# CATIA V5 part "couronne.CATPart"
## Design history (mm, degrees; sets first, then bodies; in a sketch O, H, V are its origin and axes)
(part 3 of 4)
    point P475 (-49.0081, -10.3827)
    point P476 (-49.0081, -10.3827)
    point P477 (-49.0641, -10.4563)
    point P478 (-49.0641, -10.4563)
    point P479 (-49.1276, -10.6804)
    point P480 (-49.1276, -10.6804)
    point P485 (-48.959, -11.1964)
    point P486 (-48.959, -11.1964)
    point P487 (-48.8349, -11.2887)
    point P488 (-48.8349, -11.2887)
    point P489 (-48.7903, -11.3063)
    point P490 (-48.7903, -11.3063)
    point P491 (-48.7658, -11.3115)
    point P492 (-48.7658, -11.3115)
    point P493 (-48.4661, -11.3684)
    point P494 (-48.4661, -11.3684)
    point P495 (-48.1321, -11.4258)
    point P496 (-48.1321, -11.4258)
    point P497 (-47.811, -11.4752)
    point P498 (-47.811, -11.4752)
    point P499 (-47.5029, -11.5172)
    point P500 (-47.5029, -11.5172)
    point P501 (-47.2079, -11.5521)
    point P502 (-47.2079, -11.5521)
    point P503 (-46.9261, -11.5805)
    point P504 (-46.9261, -11.5805)
    point P505 (-46.6578, -11.6028)
    point P506 (-46.6578, -11.6028)
    point P507 (-46.403, -11.6195)
    point P508 (-46.403, -11.6195)
    point P509 (-46.1619, -11.631)
    point P510 (-46.1619, -11.631)
    point P511 (-45.9345, -11.638)
    point P512 (-45.9345, -11.638)
    point P517 (-45.5064, -12.8325)
    point P518 (-45.5064, -12.8325)
    point P519 (-45.6949, -12.9469)
    point P520 (-45.6949, -12.9469)
    point P521 (-45.8932, -13.0721)
    point P522 (-45.8932, -13.0721)
    point P523 (-46.1009, -13.2083)
    point P524 (-46.1009, -13.2083)
    point P525 (-46.3177, -13.3559)
    point P526 (-46.3177, -13.3559)
    point P527 (-46.5433, -13.5153)
    point P528 (-46.5433, -13.5153)
    point P529 (-46.7773, -13.6868)
    point P530 (-46.7773, -13.6868)
    point P531 (-47.0193, -13.8709)
    point P532 (-47.0193, -13.8709)
    point P533 (-47.269, -14.0677)
    point P534 (-47.269, -14.0677)
    point P535 (-47.526, -14.2777)
    point P536 (-47.526, -14.2777)
    point P537 (-47.7899, -14.5011)
    point P538 (-47.7899, -14.5011)
    point P539 (-47.9051, -14.6021)
    point P540 (-47.9051, -14.6021)
    point P541 (-47.9167, -14.6146)
    point P542 (-47.9167, -14.6146)
    point P543 (-47.9661, -14.6927)
    point P544 (-47.9661, -14.6927)
    point P545 (-48.0098, -14.9215)
    point P546 (-48.0098, -14.9215)
    point P551 (-47.7969, -15.4209)
    point P552 (-47.7969, -15.4209)
    point P553 (-47.6652, -15.502)
    point P554 (-47.6652, -15.502)
    point P555 (-47.6192, -15.5156)
    point P556 (-47.6192, -15.5156)
    point P557 (-47.5944, -15.5187)
    point P558 (-47.5944, -15.5187)
    point P559 (-47.2908, -15.5493)
    point P560 (-47.2908, -15.5493)
    point P561 (-46.9532, -15.5773)
    point P562 (-46.9532, -15.5773)
    point P563 (-46.629, -15.5986)
    point P564 (-46.629, -15.5986)
    point P565 (-46.3183, -15.6135)
    point P566 (-46.3183, -15.6135)
    point P567 (-46.0214, -15.6226)
    point P568 (-46.0214, -15.6226)
    point P569 (-45.7383, -15.6263)
    point P570 (-45.7383, -15.6263)
    point P571 (-45.469, -15.6251)
    point P572 (-45.469, -15.6251)
    point P573 (-45.2137, -15.6195)
    point P574 (-45.2137, -15.6195)
    point P575 (-44.9725, -15.6101)
    point P576 (-44.9725, -15.6101)
    point P577 (-44.7453, -15.5972)
    point P578 (-44.7453, -15.5972)
    point P583 (-44.2148, -16.7498)
    point P584 (-44.2148, -16.7498)
    point P585 (-44.3926, -16.8803)
    point P586 (-44.3926, -16.8803)
    point P587 (-44.5793, -17.0222)
    point P588 (-44.5793, -17.0222)
    point P589 (-44.7743, -17.176)
    point P590 (-44.7743, -17.176)
    point P591 (-44.9775, -17.3419)
    point P592 (-44.9775, -17.3419)
    point P593 (-45.1883, -17.5204)
    point P594 (-45.1883, -17.5204)
    point P595 (-45.4064, -17.7117)
    point P596 (-45.4064, -17.7117)
    point P597 (-45.6314, -17.9161)
    point P598 (-45.6314, -17.9161)
    point P599 (-45.863, -18.1339)
    point P600 (-45.863, -18.1339)
    point P601 (-46.1007, -18.3655)
    point P602 (-46.1007, -18.3655)
    point P603 (-46.3442, -18.6111)
    point P604 (-46.3442, -18.6111)
    point P605 (-46.4502, -18.7218)
    point P606 (-46.4502, -18.7218)
    point P607 (-46.4606, -18.7352)
    point P608 (-46.4606, -18.7352)
    point P609 (-46.503, -18.8173)
    point P610 (-46.503, -18.8173)
    point P611 (-46.5266, -19.049)
    point P612 (-46.5266, -19.049)
    point P617 (-46.271, -19.5279)
    point P618 (-46.271, -19.5279)
    point P619 (-46.1327, -19.5973)
    point P620 (-46.1327, -19.5973)
    point P621 (-46.0858, -19.6068)
    point P622 (-46.0858, -19.6068)
    point P623 (-46.0608, -19.6078)
    point P624 (-46.0608, -19.6078)
    point P625 (-45.7556, -19.6118)
    point P626 (-45.7556, -19.6118)
    point P627 (-45.4168, -19.6103)
    point P628 (-45.4168, -19.6103)
    point P629 (-45.092, -19.6032)
    point P630 (-45.092, -19.6032)
    point P631 (-44.7813, -19.591)
    point P632 (-44.7813, -19.591)
    point P633 (-44.4847, -19.5742)
    point P634 (-44.4847, -19.5742)
    point P635 (-44.2023, -19.5532)
    point P636 (-44.2023, -19.5532)
    point P637 (-43.9342, -19.5285)
    point P638 (-43.9342, -19.5285)
    point P639 (-43.6803, -19.5007)
    point P640 (-43.6803, -19.5007)
    point P641 (-43.4409, -19.4703)
    point P642 (-43.4409, -19.4703)
    point P643 (-43.2157, -19.4376)
    point P644 (-43.2157, -19.4376)
    point P649 (-42.5867, -20.5397)
    point P650 (-42.5867, -20.5397)
    point P651 (-42.7525, -20.6851)
    point P652 (-42.7525, -20.6851)
    point P653 (-42.9261, -20.8427)
    point P654 (-42.9261, -20.8427)
    point P655 (-43.107, -21.0129)
    point P656 (-43.107, -21.0129)
    point P657 (-43.2949, -21.196)
    point P658 (-43.2949, -21.196)
    point P659 (-43.4893, -21.3921)
    point P660 (-43.4893, -21.3921)
    point P661 (-43.6899, -21.6017)
    point P662 (-43.6899, -21.6017)
    point P663 (-43.8963, -21.8249)
    point P664 (-43.8963, -21.8249)
    point P665 (-44.108, -22.0622)
    point P666 (-44.108, -22.0622)
    point P667 (-44.3246, -22.3136)
    point P668 (-44.3246, -22.3136)
    point P669 (-44.5457, -22.5794)
    point P670 (-44.5457, -22.5794)
    point P671 (-44.6417, -22.6989)
    point P672 (-44.6417, -22.6989)
    point P673 (-44.6509, -22.7132)
    point P674 (-44.6509, -22.7132)
    point P675 (-44.686, -22.7987)
    point P676 (-44.686, -22.7987)
    point P677 (-44.6894, -23.0316)
    point P678 (-44.6894, -23.0316)
    point P683 (-44.3929, -23.4864)
    point P684 (-44.3929, -23.4864)
    point P685 (-44.2491, -23.5435)
    point P686 (-44.2491, -23.5435)
    point P687 (-44.2015, -23.5489)
    point P688 (-44.2015, -23.5489)
    point P689 (-44.1766, -23.5476)
    point P690 (-44.1766, -23.5476)
    point P691 (-43.8723, -23.525)
    point P692 (-43.8723, -23.525)
    point P693 (-43.5349, -23.494)
    point P694 (-43.5349, -23.494)
    point P695 (-43.2119, -23.4586)
    point P696 (-43.2119, -23.4586)
    point P697 (-42.9034, -23.4194)
    point P698 (-42.9034, -23.4194)
    point P699 (-42.6094, -23.3768)
    point P700 (-42.6094, -23.3768)
    point P701 (-42.3299, -23.3313)
    point P702 (-42.3299, -23.3313)
    point P703 (-42.065, -23.2833)
    point P704 (-42.065, -23.2833)
    point P705 (-41.8145, -23.2335)
    point P706 (-41.8145, -23.2335)
    point P707 (-41.5786, -23.1823)
    point P708 (-41.5786, -23.1823)
    point P709 (-41.3571, -23.1302)
    point P710 (-41.3571, -23.1302)
    point P715 (-40.6345, -24.1732)
    point P716 (-40.6345, -24.1732)
    point P717 (-40.787, -24.3325)
    point P718 (-40.787, -24.3325)
    point P719 (-40.9461, -24.5047)
    point P720 (-40.9461, -24.5047)
    point P721 (-41.1115, -24.69)
    point P722 (-41.1115, -24.69)
    point P723 (-41.2828, -24.8887)
    point P724 (-41.2828, -24.8887)
    point P725 (-41.4594, -25.1011)
    point P726 (-41.4594, -25.1011)
    point P727 (-41.641, -25.3273)
    point P728 (-41.641, -25.3273)
    point P729 (-41.8271, -25.5677)
    point P730 (-41.8271, -25.5677)
    point P731 (-42.0173, -25.8225)
    point P732 (-42.0173, -25.8225)
    point P733 (-42.2112, -26.0918)
    point P734 (-42.2112, -26.0918)
    point P735 (-42.4083, -26.3759)
    point P736 (-42.4083, -26.3759)
    point P737 (-42.4935, -26.5033)
    point P738 (-42.4935, -26.5033)
    point P739 (-42.5014, -26.5183)
    point P740 (-42.5014, -26.5183)
    point P741 (-42.5289, -26.6066)
    point P742 (-42.5289, -26.6066)
    point P743 (-42.512, -26.8389)
    point P744 (-42.512, -26.8389)
    point P749 (-42.177, -27.2661)
    point P750 (-42.177, -27.2661)
    point P751 (-42.0288, -27.3105)
    point P752 (-42.0288, -27.3105)
    point P753 (-41.9809, -27.3117)
    point P754 (-41.9809, -27.3117)
    point P755 (-41.9561, -27.3083)
    point P756 (-41.9561, -27.3083)
    point P757 (-41.655, -27.2592)
    point P758 (-41.655, -27.2592)
    point P759 (-41.3216, -27.1989)
    point P760 (-41.3216, -27.1989)
    point P761 (-41.0029, -27.1355)
    point P762 (-41.0029, -27.1355)
    point P763 (-40.699, -27.0696)
    point P764 (-40.699, -27.0696)
    point P765 (-40.4098, -27.0015)
    point P766 (-40.4098, -27.0015)
    point P767 (-40.1354, -26.9318)
    point P768 (-40.1354, -26.9318)
    point P769 (-39.8756, -26.8609)
    point P770 (-39.8756, -26.8609)
    point P771 (-39.6305, -26.7895)
    point P772 (-39.6305, -26.7895)
    point P773 (-39.3999, -26.7179)
    point P774 (-39.3999, -26.7179)
    point P775 (-39.1838, -26.6466)
    point P776 (-39.1838, -26.6466)
    point P781 (-38.373, -27.6227)
    point P782 (-38.373, -27.6227)
    point P783 (-38.5111, -27.7947)
    point P784 (-38.5111, -27.7947)
    point P785 (-38.6546, -27.9801)
    point P786 (-38.6546, -27.9801)
    point P787 (-38.8032, -28.1791)
    point P788 (-38.8032, -28.1791)
    point P789 (-38.9565, -28.392)
    point P790 (-38.9565, -28.392)
    point P791 (-39.1139, -28.619)
    point P792 (-39.1139, -28.619)
    point P793 (-39.2751, -28.8602)
    point P794 (-39.2751, -28.8602)
    point P795 (-39.4396, -29.1159)
    point P796 (-39.4396, -29.1159)
    point P797 (-39.6069, -29.3863)
    point P798 (-39.6069, -29.3863)
    point P799 (-39.7765, -29.6715)
    point P800 (-39.7765, -29.6715)
    point P801 (-39.9481, -29.9716)
    point P802 (-39.9481, -29.9716)
    point P803 (-40.0218, -30.106)
    point P804 (-40.0218, -30.106)
    point P805 (-40.0285, -30.1217)
    point P806 (-40.0285, -30.1217)
    point P807 (-40.0482, -30.212)
    point P808 (-40.0482, -30.212)
    point P809 (-40.011, -30.4419)
    point P810 (-40.011, -30.4419)
    point P815 (-39.6401, -30.8384)
    point P816 (-39.6401, -30.8384)
    point P817 (-39.4886, -30.8696)
    point P818 (-39.4886, -30.8696)
    point P819 (-39.4408, -30.8666)
    point P820 (-39.4408, -30.8666)
    point P821 (-39.4164, -30.8611)
    point P822 (-39.4164, -30.8611)
    point P823 (-39.1207, -30.786)
    point P824 (-39.1207, -30.786)
    point P825 (-38.7938, -30.6968)
    point P826 (-38.7938, -30.6968)
    point P827 (-38.4819, -30.6059)
    point P828 (-38.4819, -30.6059)
    point P829 (-38.1849, -30.5137)
    point P830 (-38.1849, -30.5137)
    point P831 (-37.9027, -30.4207)
    point P832 (-37.9027, -30.4207)
    point P833 (-37.6354, -30.3273)
    point P834 (-37.6354, -30.3273)
    point P835 (-37.3828, -30.2341)
    point P836 (-37.3828, -30.2341)
    point P837 (-37.1448, -30.1416)
    point P838 (-37.1448, -30.1416)
    point P839 (-36.9214, -30.0502)
    point P840 (-36.9214, -30.0502)
    point P841 (-36.7123, -29.9603)
    point P842 (-36.7123, -29.9603)
    point P847 (-35.8195, -30.862)
    point P848 (-35.8195, -30.862)
    point P849 (-35.942, -31.0454)
    point P850 (-35.942, -31.0454)
    point P851 (-36.0689, -31.2426)
    point P852 (-36.0689, -31.2426)
    point P853 (-36.1996, -31.4538)
    point P854 (-36.1996, -31.4538)
    point P855 (-36.3337, -31.6793)
    point P856 (-36.3337, -31.6793)
    point P857 (-36.4708, -31.9191)
    point P858 (-36.4708, -31.9191)
    point P859 (-36.6103, -32.1734)
    point P860 (-36.6103, -32.1734)
    point P861 (-36.7519, -32.4425)
    point P862 (-36.7519, -32.4425)
    point P863 (-36.895, -32.7264)
    point P864 (-36.895, -32.7264)
    point P865 (-37.0391, -33.0253)
    point P866 (-37.0391, -33.0253)
    point P867 (-37.1839, -33.3393)
    point P868 (-37.1839, -33.3393)
    point P869 (-37.2456, -33.4796)
    point P870 (-37.2456, -33.4796)
    point P871 (-37.2509, -33.4958)
    point P872 (-37.2509, -33.4958)
    point P873 (-37.2626, -33.5874)
    point P874 (-37.2626, -33.5874)
    point P875 (-37.2056, -33.8133)
    point P876 (-37.2056, -33.8133)
    point P881 (-36.8016, -34.1759)
    point P882 (-36.8016, -34.1759)
    point P883 (-36.6479, -34.1938)
    point P884 (-36.6479, -34.1938)
    point P885 (-36.6005, -34.1867)
    point P886 (-36.6005, -34.1867)
    point P887 (-36.5767, -34.179)
    point P888 (-36.5767, -34.179)
    point P889 (-36.2886, -34.0784)
    point P890 (-36.2886, -34.0784)
    point P891 (-35.9708, -33.9611)
    point P892 (-35.9708, -33.9611)
    point P893 (-35.6679, -33.8434)
    point P894 (-35.6679, -33.8434)
    point P895 (-35.3801, -33.7256)
    point P896 (-35.3801, -33.7256)
    point P897 (-35.1072, -33.6083)
    point P898 (-35.1072, -33.6083)
    point P899 (-34.849, -33.492)
    point P900 (-34.849, -33.492)
    point P901 (-34.6055, -33.3772)
    point P902 (-34.6055, -33.3772)
    point P903 (-34.3765, -33.2643)
    point P904 (-34.3765, -33.2643)
    point P905 (-34.1618, -33.1537)
    point P906 (-34.1618, -33.1537)
    point P907 (-33.9614, -33.046)
    point P908 (-33.9614, -33.046)
    point P913 (-32.9934, -33.8665)
    point P914 (-32.9934, -33.8665)
    point P915 (-33.0995, -34.0598)
    point P916 (-33.0995, -34.0598)
    point P917 (-33.2087, -34.2674)
    point P918 (-33.2087, -34.2674)
    point P919 (-33.3205, -34.4892)
    point P920 (-33.3205, -34.4892)
    point P921 (-33.4344, -34.7254)
    point P922 (-33.4344, -34.7254)
    point P923 (-33.55, -34.9762)
    point P924 (-33.55, -34.9762)
    point P925 (-33.6669, -35.2418)
    point P926 (-33.6669, -35.2418)
    point P927 (-33.7845, -35.5222)
    point P928 (-33.7845, -35.5222)
    point P929 (-33.9023, -35.8175)
    point P930 (-33.9023, -35.8175)
    point P931 (-34.0199, -36.1278)
    point P932 (-34.0199, -36.1278)
    point P933 (-34.1367, -36.4532)
    point P934 (-34.1367, -36.4532)
    point P935 (-34.186, -36.5984)
    point P936 (-34.186, -36.5984)
    point P937 (-34.1898, -36.6149)
    point P938 (-34.1898, -36.6149)
    point P939 (-34.1935, -36.7073)
    point P940 (-34.1935, -36.7073)
    point P941 (-34.117, -36.9273)
    point P942 (-34.117, -36.9273)
    point P947 (-33.6829, -37.2533)
    point P948 (-33.6829, -37.2533)
    point P949 (-33.5283, -37.2577)
    point P950 (-33.5283, -37.2577)
    point P951 (-33.4817, -37.2465)
    point P952 (-33.4817, -37.2465)
    point P953 (-33.4586, -37.2368)
    point P954 (-33.4586, -37.2368)
    point P955 (-33.1804, -37.1115)
    point P956 (-33.1804, -37.1115)
    point P957 (-32.874, -36.967)
    point P958 (-32.874, -36.967)
    point P959 (-32.5826, -36.8233)
    point P960 (-32.5826, -36.8233)
    point P961 (-32.3061, -36.6809)
    point P962 (-32.3061, -36.6809)
    point P963 (-32.0444, -36.5402)
    point P964 (-32.0444, -36.5402)
    point P965 (-31.7974, -36.4019)
    point P966 (-31.7974, -36.4019)
    point P967 (-31.5648, -36.2662)
    point P968 (-31.5648, -36.2662)
    point P969 (-31.3465, -36.1338)
    point P970 (-31.3465, -36.1338)
    point P971 (-31.1423, -36.005)
    point P972 (-31.1423, -36.005)
    point P973 (-30.952, -35.8802)
    point P974 (-30.952, -35.8802)
    point P979 (-29.9162, -36.6132)
    point P980 (-29.9162, -36.6132)
    point P981 (-30.005, -36.815)
    point P982 (-30.005, -36.815)
    point P983 (-30.0957, -37.0313)
    point P984 (-30.0957, -37.0313)
    point P985 (-30.1877, -37.262)
    point P986 (-30.1877, -37.262)
    point P987 (-30.2807, -37.5073)
    point P988 (-30.2807, -37.5073)
    point P989 (-30.374, -37.7672)
    point P990 (-30.374, -37.7672)
    point P991 (-30.4673, -38.0419)
    point P992 (-30.4673, -38.0419)
    point P993 (-30.5599, -38.3315)
    point P994 (-30.5599, -38.3315)
    point P995 (-30.6516, -38.636)
    point P996 (-30.6516, -38.636)
    point P997 (-30.7417, -38.9553)
    point P998 (-30.7417, -38.9553)
    point P999 (-30.8297, -39.2897)
    point P1000 (-30.8297, -39.2897)
    point P1001 (-30.8661, -39.4386)
    point P1002 (-30.8661, -39.4386)
    point P1003 (-30.8685, -39.4554)
    point P1004 (-30.8685, -39.4554)
    point P1005 (-30.8641, -39.5478)
    point P1006 (-30.8641, -39.5478)
    point P1007 (-30.7687, -39.7603)
    point P1008 (-30.7687, -39.7603)
    point P1011 (-30.5233, -39.9645)
    point P1012 (-30.5233, -39.9645)
    point P1013 (-30.3079, -40.0472)
    point P1014 (-30.3079, -40.0472)
    point P1015 (-30.1534, -40.0381)
    point P1016 (-30.1534, -40.0381)
    point P1017 (-30.108, -40.0229)
    point P1018 (-30.108, -40.0229)
    point P1019 (-30.0859, -40.0112)
    point P1020 (-30.0859, -40.0112)
    point P1021 (-29.8197, -39.8621)
    point P1022 (-29.8197, -39.8621)
    point P1023 (-29.527, -39.6914)
    point P1024 (-29.527, -39.6914)
    point P1025 (-29.2492, -39.5229)
    point P1026 (-29.2492, -39.5229)
    point P1027 (-28.9862, -39.3569)
    point P1028 (-28.9862, -39.3569)
    point P1029 (-28.7378, -39.1941)
    point P1030 (-28.7378, -39.1941)
    point P1031 (-28.5037, -39.0347)
    point P1032 (-28.5037, -39.0347)
    point P1033 (-28.2838, -38.8793)
    point P1034 (-28.2838, -38.8793)
    point P1035 (-28.0779, -38.7283)
    point P1036 (-28.0779, -38.7283)
    point P1037 (-27.8857, -38.5822)
    point P1038 (-27.8857, -38.5822)
    point P1039 (-27.7071, -38.4413)
    point P1040 (-27.7071, -38.4413)
    point P1045 (-26.6113, -39.0812)
    point P1046 (-26.6113, -39.0812)
    point P1047 (-26.6822, -39.2901)
    point P1048 (-26.6822, -39.2901)
    point P1049 (-26.7537, -39.5134)
    point P1050 (-26.7537, -39.5134)
    point P1051 (-26.8253, -39.7512)
    point P1052 (-26.8253, -39.7512)
    point P1053 (-26.8965, -40.0037)
    point P1054 (-26.8965, -40.0037)
    point P1055 (-26.9668, -40.2708)
    point P1056 (-26.9668, -40.2708)
    point P1057 (-27.0357, -40.5526)
    point P1058 (-27.0357, -40.5526)
    point P1059 (-27.1028, -40.8491)
    point P1060 (-27.1028, -40.8491)
    point P1061 (-27.1676, -41.1604)
    point P1062 (-27.1676, -41.1604)
    point P1063 (-27.2295, -41.4864)
    point P1064 (-27.2295, -41.4864)
    point P1065 (-27.288, -41.8272)
    point P1066 (-27.288, -41.8272)
    point P1067 (-27.3114, -41.9787)
    point P1068 (-27.3114, -41.9787)
    point P1069 (-27.3122, -41.9957)
    point P1070 (-27.3122, -41.9957)
    point P1071 (-27.2999, -42.0873)
    point P1072 (-27.2999, -42.0873)
    point P1073 (-27.1863, -42.2906)
    point P1074 (-27.1863, -42.2906)
    point P1079 (-26.7022, -42.5363)
    point P1080 (-26.7022, -42.5363)
    point P1081 (-26.5491, -42.5138)
    point P1082 (-26.5491, -42.5138)
    point P1083 (-26.5052, -42.4947)
    point P1084 (-26.5052, -42.4947)
    point P1085 (-26.4842, -42.4811)
    point P1086 (-26.4842, -42.4811)
    point P1087 (-26.232, -42.3094)
    point P1088 (-26.232, -42.3094)
    point P1089 (-25.9553, -42.1138)
    point P1090 (-25.9553, -42.1138)
    point P1091 (-25.6933, -41.9217)
    point P1092 (-25.6933, -41.9217)
    point P1093 (-25.4457, -41.7335)
    point P1094 (-25.4457, -41.7335)
    point P1095 (-25.2124, -41.5496)
    point P1096 (-25.2124, -41.5496)
    point P1097 (-24.9932, -41.3704)
    point P1098 (-24.9932, -41.3704)
    point P1099 (-24.7877, -41.1964)
    point P1100 (-24.7877, -41.1964)
    point P1101 (-24.5957, -41.0281)
    point P1102 (-24.5957, -41.0281)
    point P1103 (-24.417, -40.8658)
    point P1104 (-24.417, -40.8658)
    point P1105 (-24.2513, -40.7099)
    point P1106 (-24.2513, -40.7099)
    point P1111 (-23.1039, -41.2518)
    point P1112 (-23.1039, -41.2518)
    point P1113 (-23.1563, -41.4661)
    point P1114 (-23.1563, -41.4661)
    point P1115 (-23.2081, -41.6948)
    point P1116 (-23.2081, -41.6948)
    point P1117 (-23.2586, -41.9379)
    point P1118 (-23.2586, -41.9379)
    point P1119 (-23.3076, -42.1956)
    point P1120 (-23.3076, -42.1956)
    point P1121 (-23.3543, -42.4678)
    point P1122 (-23.3543, -42.4678)
    point P1123 (-23.3985, -42.7546)
    point P1124 (-23.3985, -42.7546)
    point P1125 (-23.4395, -43.0558)
    point P1126 (-23.4395, -43.0558)
    point P1127 (-23.4768, -43.3716)
    point P1128 (-23.4768, -43.3716)
    point P1129 (-23.5101, -43.7018)
    point P1130 (-23.5101, -43.7018)
    point P1131 (-23.5387, -44.0463)
    point P1132 (-23.5387, -44.0463)
    point P1133 (-23.5487, -44.1993)
    point P1134 (-23.5487, -44.1993)
    point P1135 (-23.5481, -44.2163)
    point P1136 (-23.5481, -44.2163)
    point P1137 (-23.5278, -44.3064)
    point P1138 (-23.5278, -44.3064)
    point P1139 (-23.397, -44.4992)
    point P1140 (-23.397, -44.4992)
    point P1145 (-22.8933, -44.7017)
    point P1146 (-22.8933, -44.7017)
    point P1147 (-22.7428, -44.666)
    point P1148 (-22.7428, -44.666)
    point P1149 (-22.7007, -44.6431)
    point P1150 (-22.7007, -44.6431)
    point P1151 (-22.6809, -44.6277)
    point P1152 (-22.6809, -44.6277)
    point P1153 (-22.4447, -44.4347)
    point P1154 (-22.4447, -44.4347)
    point P1155 (-22.1861, -44.2157)
    point P1156 (-22.1861, -44.2157)
    point P1157 (-21.9418, -44.0015)
    point P1158 (-21.9418, -44.0015)
    point P1159 (-21.7116, -43.7924)
    point P1160 (-21.7116, -43.7924)
    point P1161 (-21.4952, -43.5889)
    point P1162 (-21.4952, -43.5889)
    point P1163 (-21.2924, -43.3913)
    point P1164 (-21.2924, -43.3913)
    point P1165 (-21.1028, -43.2001)
    point P1166 (-21.1028, -43.2001)
    point P1167 (-20.9263, -43.0156)
    point P1168 (-20.9263, -43.0156)
    point P1169 (-20.7624, -42.8383)
    point P1170 (-20.7624, -42.8383)
    point P1171 (-20.6109, -42.6686)
    point P1172 (-20.6109, -42.6686)
    point P1173 (-20.5191, -42.5621)
    point P1174 (-20.5191, -42.5621)
    point P1177 (-19.4206, -43.1085)
    point P1178 (-19.4206, -43.1085)
    point P1179 (-19.4542, -43.3265)
    point P1180 (-19.4542, -43.3265)
    point P1181 (-19.4858, -43.5588)
    point P1182 (-19.4858, -43.5588)
    point P1183 (-19.515, -43.8055)
    point P1184 (-19.515, -43.8055)
    point P1185 (-19.5413, -44.0664)
    point P1186 (-19.5413, -44.0664)
    point P1187 (-19.5642, -44.3417)
    point P1188 (-19.5642, -44.3417)
    point P1189 (-19.5831, -44.6312)
    point P1190 (-19.5831, -44.6312)
    point P1191 (-19.5977, -44.9349)
    point P1192 (-19.5977, -44.9349)
    point P1193 (-19.6074, -45.2527)
    point P1194 (-19.6074, -45.2527)
    point P1195 (-19.6118, -45.5845)
    point P1196 (-19.6118, -45.5845)
    point P1197 (-19.6103, -45.9303)
    point P1198 (-19.6103, -45.9303)
    point P1199 (-19.6069, -46.0835)
    point P1200 (-19.6069, -46.0835)
    point P1201 (-19.6048, -46.1004)
    point P1202 (-19.6048, -46.1004)
    point P1203 (-19.5768, -46.1884)
    point P1204 (-19.5768, -46.1884)
    point P1205 (-19.4296, -46.369)
    point P1206 (-19.4296, -46.369)
    point P1211 (-18.9102, -46.5269)
    point P1212 (-18.9102, -46.5269)
    point P1213 (-18.7634, -46.4782)
    point P1214 (-18.7634, -46.4782)
    point P1215 (-18.7234, -46.4517)
    point P1216 (-18.7234, -46.4517)
    point P1217 (-18.7051, -46.4347)
    point P1218 (-18.7051, -46.4347)
    point P1219 (-18.4865, -46.2217)
    point P1220 (-18.4865, -46.2217)
    point P1221 (-18.248, -45.9811)
    point P1222 (-18.248, -45.9811)
    point P1223 (-18.0233, -45.7464)
    point P1224 (-18.0233, -45.7464)
    point P1225 (-17.8122, -45.5181)
    point P1226 (-17.8122, -45.5181)
    point P1227 (-17.6144, -45.2964)
    point P1228 (-17.6144, -45.2964)
    point P1229 (-17.4296, -45.0819)
    point P1230 (-17.4296, -45.0819)
    point P1231 (-17.2574, -44.8749)
    point P1232 (-17.2574, -44.8749)
    point P1233 (-17.0976, -44.6758)
    point P1234 (-17.0976, -44.6758)
    point P1235 (-16.9498, -44.4849)
    point P1236 (-16.9498, -44.4849)
    point P1237 (-16.8136, -44.3026)
    point P1238 (-16.8136, -44.3026)
    point P1243 (-15.5896, -44.6371)
    point P1244 (-15.5896, -44.6371)
    point P1245 (-15.604, -44.8572)
    point P1246 (-15.604, -44.8572)
    point P1247 (-15.6153, -45.0914)
    point P1248 (-15.6153, -45.0914)
    point P1249 (-15.6228, -45.3396)
    point P1250 (-15.6228, -45.3396)
    point P1251 (-15.6263, -45.6019)
    point P1252 (-15.6263, -45.6019)
    point P1253 (-15.6251, -45.8781)
    point P1254 (-15.6251, -45.8781)
    point P1255 (-15.6187, -46.1681)
    point P1256 (-15.6187, -46.1681)
    point P1257 (-15.6068, -46.4719)
    point P1258 (-15.6068, -46.4719)
    point P1259 (-15.5888, -46.7894)
    point P1260 (-15.5888, -46.7894)
    point P1261 (-15.5642, -47.1203)
    point P1262 (-15.5642, -47.1203)
    point P1263 (-15.5326, -47.4646)
    point P1264 (-15.5326, -47.4646)
    point P1265 (-15.5159, -47.617)
    point P1266 (-15.5159, -47.617)
    point P1267 (-15.5123, -47.6336)
    point P1268 (-15.5123, -47.6336)
    point P1269 (-15.4767, -47.7189)
    point P1270 (-15.4767, -47.7189)
    point P1271 (-15.3143, -47.886)
    point P1272 (-15.3143, -47.886)
    point P1277 (-14.7831, -47.998)
    point P1278 (-14.7831, -47.998)
    point P1279 (-14.6411, -47.9366)
    point P1280 (-14.6411, -47.9366)
    point P1281 (-14.6036, -47.9068)
    point P1282 (-14.6036, -47.9068)
    point P1283 (-14.5869, -47.8882)
    point P1284 (-14.5869, -47.8882)
    point P1285 (-14.3877, -47.6571)
    point P1286 (-14.3877, -47.6571)
    point P1287 (-14.171, -47.3966)
    point P1288 (-14.171, -47.3966)
    point P1289 (-13.9677, -47.1432)
    point P1290 (-13.9677, -47.1432)
    point P1291 (-13.7773, -46.8973)
    point P1292 (-13.7773, -46.8973)
    point P1293 (-13.5995, -46.6593)
    point P1294 (-13.5995, -46.6593)
    point P1295 (-13.4341, -46.4295)
    point P1296 (-13.4341, -46.4295)
    point P1297 (-13.2806, -46.2082)
    point P1298 (-13.2806, -46.2082)
    point P1299 (-13.1388, -45.9959)
    point P1300 (-13.1388, -45.9959)
    point P1301 (-13.0081, -45.7929)
    point P1302 (-13.0081, -45.7929)
    point P1303 (-12.8884, -45.5994)
    point P1304 (-12.8884, -45.5994)
    point P1309 (-11.6399, -45.8259)
    point P1310 (-11.6399, -45.8259)
    point P1311 (-11.6351, -46.0464)
    point P1312 (-11.6351, -46.0464)
    point P1313 (-11.6259, -46.2807)
    point P1314 (-11.6259, -46.2807)
    point P1315 (-11.6118, -46.5287)
    point P1316 (-11.6118, -46.5287)
    point P1317 (-11.5923, -46.7903)
    point P1318 (-11.5923, -46.7903)
    point P1319 (-11.5671, -47.0653)
    point P1320 (-11.5671, -47.0653)
    point P1321 (-11.5355, -47.3537)
    point P1322 (-11.5355, -47.3537)
    point P1323 (-11.4971, -47.6553)
    point P1324 (-11.4971, -47.6553)
    point P1325 (-11.4515, -47.97)
    point P1326 (-11.4515, -47.97)
    point P1327 (-11.3982, -48.2975)
    point P1328 (-11.3982, -48.2975)
    point P1329 (-11.3366, -48.6378)
    point P1330 (-11.3366, -48.6378)
    point P1331 (-11.3067, -48.7881)
    point P1332 (-11.3067, -48.7881)
    point P1333 (-11.3017, -48.8043)
    point P1334 (-11.3017, -48.8043)
    point P1335 (-11.2588, -48.8862)
    point P1336 (-11.2588, -48.8862)
    point P1337 (-11.0825, -49.0385)
    point P1338 (-11.0825, -49.0385)
    point P1343 (-10.5436, -49.1037)
    point P1344 (-10.5436, -49.1037)
    point P1345 (-10.4075, -49.0303)
    point P1346 (-10.4075, -49.0303)
    point P1347 (-10.3727, -48.9973)
    point P1348 (-10.3727, -48.9973)
    point P1349 (-10.3576, -48.9773)
    point P1350 (-10.3576, -48.9773)
    point P1351 (-10.1793, -48.7297)
    point P1352 (-10.1793, -48.7297)
    point P1353 (-9.9862, -48.4513)
    point P1354 (-9.9862, -48.4513)
    point P1355 (-9.8057, -48.1812)
    point P1356 (-9.8057, -48.1812)
    point P1357 (-9.6375, -47.9196)
    point P1358 (-9.6375, -47.9196)
    point P1359 (-9.4811, -47.667)
    point P1360 (-9.4811, -47.667)
    point P1361 (-9.3364, -47.4236)
    point P1362 (-9.3364, -47.4236)
    point P1363 (-9.2028, -47.1899)
    point P1364 (-9.2028, -47.1899)
    point P1365 (-9.0799, -46.966)
    point P1366 (-9.0799, -46.966)
    point P1367 (-8.9675, -46.7523)
    point P1368 (-8.9675, -46.7523)
    point P1369 (-8.8651, -46.5492)
    point P1370 (-8.8651, -46.5492)
    point P1375 (-7.6016, -46.666)
    point P1376 (-7.6016, -46.666)
    point P1377 (-7.5776, -46.8853)
    point P1378 (-7.5776, -46.8853)
    point P1379 (-7.548, -47.1179)
    point P1380 (-7.548, -47.1179)
    point P1381 (-7.5124, -47.3637)
    point P1382 (-7.5124, -47.3637)
    point P1383 (-7.4702, -47.6226)
    point P1384 (-7.4702, -47.6226)
    point P1385 (-7.421, -47.8944)
    point P1386 (-7.421, -47.8944)
    point P1387 (-7.3644, -48.1789)
    point P1388 (-7.3644, -48.1789)
    point P1389 (-7.2999, -48.476)
    point P1390 (-7.2999, -48.476)
    point P1391 (-7.2271, -48.7855)
    point P1392 (-7.2271, -48.7855)
    point P1393 (-7.1454, -49.1071)
    point P1394 (-7.1454, -49.1071)
    point P1395 (-7.0544, -49.4407)
    point P1396 (-7.0544, -49.4407)
    point P1397 (-7.0115, -49.5879)
    point P1398 (-7.0115, -49.5879)
    point P1399 (-7.0052, -49.6036)
    point P1400 (-7.0052, -49.6036)
    point P1401 (-6.9552, -49.6814)
    point P1402 (-6.9552, -49.6814)
    point P1403 (-6.7664, -49.8178)
    point P1404 (-6.7664, -49.8178)
    point P1409 (-6.2238, -49.8358)
    point P1410 (-6.2238, -49.8358)
    point P1411 (-6.0946, -49.7508)
    point P1412 (-6.0946, -49.7508)
    point P1413 (-6.0629, -49.7149)
    point P1414 (-6.0629, -49.7149)
    point P1415 (-6.0495, -49.6937)
    point P1416 (-6.0495, -49.6937)
    point P1417 (-5.8935, -49.4314)
    point P1418 (-5.8935, -49.4314)
    point P1419 (-5.7254, -49.1373)
    point P1420 (-5.7254, -49.1373)
    point P1421 (-5.5691, -48.8524)
    point P1422 (-5.5691, -48.8524)
    point P1423 (-5.4243, -48.5772)
    point P1424 (-5.4243, -48.5772)
    point P1425 (-5.2906, -48.3119)
    point P1426 (-5.2906, -48.3119)
    point P1427 (-5.1676, -48.0569)
    point P1428 (-5.1676, -48.0569)
    point P1429 (-5.0549, -47.8124)
    point P1430 (-5.0549, -47.8124)
    point P1431 (-4.952, -47.5787)
    point P1432 (-4.952, -47.5787)
    point P1433 (-4.8587, -47.356)
    point P1434 (-4.8587, -47.356)
    point P1435 (-4.7744, -47.1447)
    point P1436 (-4.7744, -47.1447)
    point P1441 (-3.5055, -47.151)
    point P1442 (-3.5055, -47.151)
    point P1443 (-3.4624, -47.3673)
    point P1444 (-3.4624, -47.3673)
    point P1445 (-3.4127, -47.5964)
    point P1446 (-3.4127, -47.5964)
    point P1447 (-3.3558, -47.8382)
    point P1448 (-3.3558, -47.8382)
    point P1449 (-3.2912, -48.0924)
    point P1450 (-3.2912, -48.0924)
    point P1451 (-3.2185, -48.3589)
    point P1452 (-3.2185, -48.3589)
    point P1453 (-3.1374, -48.6374)
    point P1454 (-3.1374, -48.6374)
    point P1455 (-3.0472, -48.9278)
    point P1456 (-3.0472, -48.9278)
    point P1457 (-2.9476, -49.2297)
    point P1458 (-2.9476, -49.2297)
    point P1459 (-2.8382, -49.543)
    point P1460 (-2.8382, -49.543)
    point P1461 (-2.7185, -49.8674)
    point P1462 (-2.7185, -49.8674)
    point P1463 (-2.663, -50.0103)
    point P1464 (-2.663, -50.0103)
    point P1465 (-2.6553, -50.0254)
    point P1466 (-2.6553, -50.0254)
    point P1467 (-2.5988, -50.0986)
    point P1468 (-2.5988, -50.0986)
    point P1469 (-2.3987, -50.2179)
    point P1470 (-2.3987, -50.2179)
    point P1471 (-2.2991, -50.2349)
    point P1472 (-2.2991, -50.2349)
    point P1475 (-1.8566, -50.1886)
    point P1476 (-1.8566, -50.1886)
    point P1477 (-1.7353, -50.0926)
    point P1478 (-1.7353, -50.0926)
    point P1479 (-1.7068, -50.0541)
    point P1480 (-1.7068, -50.0541)
    point P1481 (-1.6954, -50.0318)
    point P1482 (-1.6954, -50.0318)
    point P1483 (-1.5629, -49.757)
    point P1484 (-1.5629, -49.757)
    point P1485 (-1.421, -49.4493)
    point P1486 (-1.421, -49.4493)
    point P1487 (-1.2902, -49.1519)
    point P1488 (-1.2902, -49.1519)
    point P1489 (-1.1699, -48.8651)
    point P1490 (-1.1699, -48.8651)
    point P1491 (-1.0598, -48.5892)
    point P1492 (-1.0598, -48.5892)
    point P1493 (-0.9595, -48.3244)
    point P1494 (-0.9595, -48.3244)
    point P1495 (-0.8685, -48.071)
    point P1496 (-0.8685, -48.071)
    point P1497 (-0.7864, -47.8292)
    point P1498 (-0.7864, -47.8292)
    point P1499 (-0.7128, -47.5993)
    point P1500 (-0.7128, -47.5993)
    point P1501 (-0.6473, -47.3814)
    point P1502 (-0.6473, -47.3814)
    point P1507 (0.6174, -47.2771)
    point P1508 (0.6174, -47.2771)
    point P1509 (0.6791, -47.4888)
    point P1510 (0.6791, -47.4888)
    point P1511 (0.7486, -47.7127)
    point P1512 (0.7486, -47.7127)
    point P1513 (0.8264, -47.9486)
    point P1514 (0.8264, -47.9486)
    point P1515 (0.9129, -48.1963)
    point P1516 (0.9129, -48.1963)
    point P1517 (1.0085, -48.4554)
    point P1518 (1.0085, -48.4554)
    point P1519 (1.1136, -48.7258)
    point P1520 (1.1136, -48.7258)
    point P1521 (1.2287, -49.0072)
    point P1522 (1.2287, -49.0072)
    point P1523 (1.3542, -49.2993)
    point P1524 (1.3542, -49.2993)
    point P1525 (1.4905, -49.6019)
    point P1526 (1.4905, -49.6019)
    point P1527 (1.638, -49.9146)
    point P1528 (1.638, -49.9146)
    point P1529 (1.7058, -50.0521)
    point P1530 (1.7058, -50.0521)
    point P1531 (1.7148, -50.0665)
    point P1532 (1.7148, -50.0665)
    point P1533 (1.7775, -50.1344)
    point P1534 (1.7775, -50.1344)
    point P1535 (1.9872, -50.2359)
    point P1536 (1.9872, -50.2359)
    point P1541 (2.5247, -50.1595)
    point P1542 (2.5247, -50.1595)
    point P1543 (2.6371, -50.0532)
    point P1544 (2.6371, -50.0532)
    point P1545 (2.6622, -50.0124)
    point P1546 (2.6622, -50.0124)
    point P1547 (2.6716, -49.9892)
    point P1548 (2.6716, -49.9892)
    point P1549 (2.7797, -49.7039)
    point P1550 (2.7797, -49.7039)
    point P1551 (2.8942, -49.385)
    point P1552 (2.8942, -49.385)
    point P1553 (2.9986, -49.0773)
    point P1554 (2.9986, -49.0773)
    point P1555 (3.0934, -48.7811)
    point P1556 (3.0934, -48.7811)
    point P1557 (3.179, -48.4967)
    point P1558 (3.179, -48.4967)
    point P1559 (3.2559, -48.2241)
    point P1560 (3.2559, -48.2241)
    point P1561 (3.3245, -47.9638)
    point P1562 (3.3245, -47.9638)
    point P1563 (3.3851, -47.7157)
    point P1564 (3.3851, -47.7157)
    point P1565 (3.4384, -47.4803)
    point P1566 (3.4384, -47.4803)
    point P1567 (3.4848, -47.2575)
    point P1568 (3.4848, -47.2575)
    point P1573 (4.7355, -47.0434)
    point P1574 (4.7355, -47.0434)
    point P1575 (4.8154, -47.2489)
    point P1576 (4.8154, -47.2489)
    point P1577 (4.9042, -47.4659)
    point P1578 (4.9042, -47.4659)
    point P1579 (5.0022, -47.6941)
    point P1580 (5.0022, -47.6941)
    point P1581 (5.11, -47.9333)
    point P1582 (5.11, -47.9333)
    point P1583 (5.2278, -48.1831)
    point P1584 (5.2278, -48.1831)
    point P1585 (5.3561, -48.4433)
    point P1586 (5.3561, -48.4433)
    point P1587 (5.4953, -48.7136)
    point P1588 (5.4953, -48.7136)
    point P1589 (5.6458, -48.9937)
    point P1590 (5.6458, -48.9937)
    point P1591 (5.808, -49.2832)
    point P1592 (5.808, -49.2832)
    point P1593 (5.9822, -49.5819)
    point P1594 (5.9822, -49.5819)
    point P1595 (6.0617, -49.713)
    point P1596 (6.0617, -49.713)
    point P1597 (6.0719, -49.7265)
    point P1598 (6.0719, -49.7265)
    point P1599 (6.1403, -49.7887)
    point P1600 (6.1403, -49.7887)
    point P1601 (6.358, -49.8715)
    point P1602 (6.358, -49.8715)
    point P1607 (6.8867, -49.7486)
    point P1608 (6.8867, -49.7486)
    point P1609 (6.9895, -49.6329)
    point P1610 (6.9895, -49.6329)
    point P1611 (7.0109, -49.59)
    point P1612 (7.0109, -49.59)
    point P1613 (7.0183, -49.5661)
    point P1614 (7.0183, -49.5661)
    point P1615 (7.1011, -49.2725)
    point P1616 (7.1011, -49.2725)
    point P1617 (7.1873, -48.9448)
    point P1618 (7.1873, -48.9448)
    point P1619 (7.2646, -48.6292)
    point P1620 (7.2646, -48.6292)
    point P1621 (7.3332, -48.3259)
    point P1622 (7.3332, -48.3259)
    point P1623 (7.3937, -48.0351)
    point P1624 (7.3937, -48.0351)
    point P1625 (7.4465, -47.7569)
    point P1626 (7.4465, -47.7569)
    point P1627 (7.4921, -47.4915)
    point P1628 (7.4921, -47.4915)
    point P1629 (7.531, -47.2391)
    point P1630 (7.531, -47.2391)
    point P1631 (7.5635, -46.9999)
    point P1632 (7.5635, -46.9999)
    point P1633 (7.5903, -46.774)
    point P1634 (7.5903, -46.774)
    point P1639 (8.8176, -46.4516)
    point P1640 (8.8176, -46.4516)
    point P1641 (8.9151, -46.6494)
    point P1642 (8.9151, -46.6494)
    point P1643 (9.0225, -46.8579)
    point P1644 (9.0225, -46.8579)
    point P1645 (9.14, -47.0767)
    point P1646 (9.14, -47.0767)
    point P1647 (9.2682, -47.3055)
    point P1648 (9.2682, -47.3055)
    point P1649 (9.4073, -47.5441)
    point P1650 (9.4073, -47.5441)
    point P1651 (9.5578, -47.7922)
    point P1652 (9.5578, -47.7922)
    point P1653 (9.7201, -48.0493)
    point P1654 (9.7201, -48.0493)
    point P1655 (9.8944, -48.3152)
    point P1656 (9.8944, -48.3152)
    point P1657 (10.0812, -48.5895)
    point P1658 (10.0812, -48.5895)
    point P1659 (10.2807, -48.8719)
    point P1660 (10.2807, -48.8719)
    point P1661 (10.3714, -48.9955)
    point P1662 (10.3714, -48.9955)
    point P1663 (10.3827, -49.0081)
    point P1664 (10.3827, -49.0081)
    point P1665 (10.4563, -49.0641)
    point P1666 (10.4563, -49.0641)
    point P1667 (10.6804, -49.1276)
    point P1668 (10.6804, -49.1276)
    point P1673 (11.1964, -48.959)
    point P1674 (11.1964, -48.959)
    point P1675 (11.2887, -48.8349)
    point P1676 (11.2887, -48.8349)
    point P1677 (11.3063, -48.7903)
    point P1678 (11.3063, -48.7903)
    point P1679 (11.3115, -48.7658)
    point P1680 (11.3115, -48.7658)
    point P1681 (11.3684, -48.4661)
    point P1682 (11.3684, -48.4661)
    point P1683 (11.4258, -48.1321)
    point P1684 (11.4258, -48.1321)
    point P1685 (11.4752, -47.811)
    point P1686 (11.4752, -47.811)
    point P1687 (11.5172, -47.5029)
    point P1688 (11.5172, -47.5029)
    point P1689 (11.5521, -47.2079)
    point P1690 (11.5521, -47.2079)
    point P1691 (11.5805, -46.9261)
    point P1692 (11.5805, -46.9261)
    point P1693 (11.6028, -46.6578)
    point P1694 (11.6028, -46.6578)
    point P1695 (11.6195, -46.403)
    point P1696 (11.6195, -46.403)
    point P1697 (11.631, -46.1619)
    point P1698 (11.631, -46.1619)
    point P1699 (11.638, -45.9345)
    point P1700 (11.638, -45.9345)
    point P1705 (12.8325, -45.5064)
    point P1706 (12.8325, -45.5064)
    point P1707 (12.9469, -45.6949)
    point P1708 (12.9469, -45.6949)
    point P1709 (13.0721, -45.8932)
    point P1710 (13.0721, -45.8932)
    point P1711 (13.2083, -46.1009)
    point P1712 (13.2083, -46.1009)
    point P1713 (13.3559, -46.3177)
    point P1714 (13.3559, -46.3177)
    point P1715 (13.5153, -46.5433)
    point P1716 (13.5153, -46.5433)
    point P1717 (13.6868, -46.7773)
    point P1718 (13.6868, -46.7773)
    point P1719 (13.8709, -47.0193)
    point P1720 (13.8709, -47.0193)
    point P1721 (14.0677, -47.269)
    point P1722 (14.0677, -47.269)
    point P1723 (14.2777, -47.526)
    point P1724 (14.2777, -47.526)
    point P1725 (14.5011, -47.7899)
    point P1726 (14.5011, -47.7899)
    point P1727 (14.6021, -47.9051)
    point P1728 (14.6021, -47.9051)
    point P1729 (14.6146, -47.9167)
    point P1730 (14.6146, -47.9167)
    point P1731 (14.6927, -47.9661)
    point P1732 (14.6927, -47.9661)
    point P1733 (14.9215, -48.0098)
    point P1734 (14.9215, -48.0098)
    point P1739 (15.4209, -47.7969)
    point P1740 (15.4209, -47.7969)
    point P1741 (15.502, -47.6652)
    point P1742 (15.502, -47.6652)
    point P1743 (15.5156, -47.6192)
    point P1744 (15.5156, -47.6192)
    point P1745 (15.5187, -47.5944)
    point P1746 (15.5187, -47.5944)
    point P1747 (15.5493, -47.2908)
    point P1748 (15.5493, -47.2908)
    point P1749 (15.5773, -46.9532)
    point P1750 (15.5773, -46.9532)
    point P1751 (15.5986, -46.629)
    point P1752 (15.5986, -46.629)
    point P1753 (15.6135, -46.3183)
    point P1754 (15.6135, -46.3183)
    point P1755 (15.6226, -46.0214)
    point P1756 (15.6226, -46.0214)
    point P1757 (15.6263, -45.7383)
    point P1758 (15.6263, -45.7383)
    point P1759 (15.6251, -45.469)
    point P1760 (15.6251, -45.469)
    point P1761 (15.6195, -45.2137)
    point P1762 (15.6195, -45.2137)
    point P1763 (15.6101, -44.9725)
    point P1764 (15.6101, -44.9725)
    point P1765 (15.5972, -44.7453)
    point P1766 (15.5972, -44.7453)
    point P1771 (16.7498, -44.2148)
    point P1772 (16.7498, -44.2148)
    point P1773 (16.8803, -44.3926)
    point P1774 (16.8803, -44.3926)
    point P1775 (17.0222, -44.5793)
    point P1776 (17.0222, -44.5793)
    point P1777 (17.176, -44.7743)
    point P1778 (17.176, -44.7743)
    point P1779 (17.3419, -44.9775)
    point P1780 (17.3419, -44.9775)
    point P1781 (17.5204, -45.1883)
    point P1782 (17.5204, -45.1883)
    point P1783 (17.7117, -45.4064)
    point P1784 (17.7117, -45.4064)
    point P1785 (17.9161, -45.6314)
    point P1786 (17.9161, -45.6314)
    point P1787 (18.1339, -45.863)
    point P1788 (18.1339, -45.863)
    point P1789 (18.3655, -46.1007)
    point P1790 (18.3655, -46.1007)
    point P1791 (18.6111, -46.3442)
    point P1792 (18.6111, -46.3442)
    point P1793 (18.7218, -46.4502)
    point P1794 (18.7218, -46.4502)
    point P1795 (18.7352, -46.4606)
    point P1796 (18.7352, -46.4606)
    point P1797 (18.8173, -46.503)
    point P1798 (18.8173, -46.503)
    point P1799 (19.049, -46.5266)
    point P1800 (19.049, -46.5266)
    point P1805 (19.5279, -46.271)
    point P1806 (19.5279, -46.271)
    point P1807 (19.5973, -46.1327)
    point P1808 (19.5973, -46.1327)
    point P1809 (19.6068, -46.0858)
    point P1810 (19.6068, -46.0858)
    point P1811 (19.6078, -46.0608)
    point P1812 (19.6078, -46.0608)
    point P1813 (19.6118, -45.7556)
    point P1814 (19.6118, -45.7556)
    point P1815 (19.6103, -45.4168)
    point P1816 (19.6103, -45.4168)
    point P1817 (19.6032, -45.092)
    point P1818 (19.6032, -45.092)
    point P1819 (19.591, -44.7813)
    point P1820 (19.591, -44.7813)
    point P1821 (19.5742, -44.4847)
    point P1822 (19.5742, -44.4847)
    point P1823 (19.5532, -44.2023)
    point P1824 (19.5532, -44.2023)
    point P1825 (19.5285, -43.9342)
    point P1826 (19.5285, -43.9342)
    point P1827 (19.5007, -43.6803)
    point P1828 (19.5007, -43.6803)
    point P1829 (19.4703, -43.4409)
    point P1830 (19.4703, -43.4409)
    point P1831 (19.4376, -43.2157)
    point P1832 (19.4376, -43.2157)
    point P1837 (20.5397, -42.5867)
    point P1838 (20.5397, -42.5867)
    point P1839 (20.6851, -42.7525)
    point P1840 (20.6851, -42.7525)
    point P1841 (20.8427, -42.9261)
    point P1842 (20.8427, -42.9261)
    point P1843 (21.0129, -43.107)
    point P1844 (21.0129, -43.107)
    point P1845 (21.196, -43.2949)
    point P1846 (21.196, -43.2949)
    point P1847 (21.3921, -43.4893)
    point P1848 (21.3921, -43.4893)
    point P1849 (21.6017, -43.6899)
    point P1850 (21.6017, -43.6899)
    point P1851 (21.8249, -43.8963)
    point P1852 (21.8249, -43.8963)
    point P1853 (22.0622, -44.108)
    point P1854 (22.0622, -44.108)
    point P1855 (22.3136, -44.3246)
    point P1856 (22.3136, -44.3246)
    point P1857 (22.5794, -44.5457)
    point P1858 (22.5794, -44.5457)
    point P1859 (22.6989, -44.6417)
    point P1860 (22.6989, -44.6417)
    point P1861 (22.7132, -44.6509)
    point P1862 (22.7132, -44.6509)
    point P1863 (22.7987, -44.686)
    point P1864 (22.7987, -44.686)
    point P1865 (23.0316, -44.6894)
    point P1866 (23.0316, -44.6894)
    point P1869 (23.3204, -44.5532)
    point P1870 (23.3204, -44.5532)
    point P1871 (23.4864, -44.3929)
    point P1872 (23.4864, -44.3929)
    point P1873 (23.5435, -44.2491)
    point P1874 (23.5435, -44.2491)
    point P1875 (23.5489, -44.2015)
    point P1876 (23.5489, -44.2015)
    point P1877 (23.5476, -44.1766)
    point P1878 (23.5476, -44.1766)
    point P1879 (23.525, -43.8723)
    point P1880 (23.525, -43.8723)
    point P1881 (23.494, -43.5349)
    point P1882 (23.494, -43.5349)
    point P1883 (23.4586, -43.2119)
    point P1884 (23.4586, -43.2119)
    point P1885 (23.4194, -42.9034)
    point P1886 (23.4194, -42.9034)
    point P1887 (23.3768, -42.6094)
    point P1888 (23.3768, -42.6094)
    point P1889 (23.3313, -42.3299)
    point P1890 (23.3313, -42.3299)
    point P1891 (23.2833, -42.065)
    point P1892 (23.2833, -42.065)
    point P1893 (23.2335, -41.8145)
    point P1894 (23.2335, -41.8145)
    point P1895 (23.1823, -41.5786)
    point P1896 (23.1823, -41.5786)
    point P1897 (23.1302, -41.3571)
    point P1898 (23.1302, -41.3571)
    point P1903 (24.1732, -40.6345)
    point P1904 (24.1732, -40.6345)
    point P1905 (24.3325, -40.787)
    point P1906 (24.3325, -40.787)
    point P1907 (24.5047, -40.9461)
    point P1908 (24.5047, -40.9461)
    point P1909 (24.69, -41.1115)
    point P1910 (24.69, -41.1115)
    point P1911 (24.8887, -41.2828)
    point P1912 (24.8887, -41.2828)
    point P1913 (25.1011, -41.4594)
    point P1914 (25.1011, -41.4594)
    point P1915 (25.3273, -41.641)
    point P1916 (25.3273, -41.641)
    point P1917 (25.5677, -41.8271)
    point P1918 (25.5677, -41.8271)
    point P1919 (25.8225, -42.0173)
    point P1920 (25.8225, -42.0173)
    point P1921 (26.0918, -42.2112)
    point P1922 (26.0918, -42.2112)
    point P1923 (26.3759, -42.4083)
    point P1924 (26.3759, -42.4083)
    point P1925 (26.5033, -42.4935)
    point P1926 (26.5033, -42.4935)
    point P1927 (26.5183, -42.5014)
    point P1928 (26.5183, -42.5014)
    point P1929 (26.6066, -42.5289)
    point P1930 (26.6066, -42.5289)
    point P1931 (26.8389, -42.512)
    point P1932 (26.8389, -42.512)
    point P1937 (27.2661, -42.177)
    point P1938 (27.2661, -42.177)
    point P1939 (27.3105, -42.0288)
    point P1940 (27.3105, -42.0288)
    point P1941 (27.3117, -41.9809)
    point P1942 (27.3117, -41.9809)
    point P1943 (27.3083, -41.9561)
    point P1944 (27.3083, -41.9561)
    point P1945 (27.2592, -41.655)
    point P1946 (27.2592, -41.655)
    point P1947 (27.1989, -41.3216)
    point P1948 (27.1989, -41.3216)
    point P1949 (27.1355, -41.0029)
    point P1950 (27.1355, -41.0029)
    point P1951 (27.0696, -40.699)
    point P1952 (27.0696, -40.699)
    point P1953 (27.0015, -40.4098)
    point P1954 (27.0015, -40.4098)
    point P1955 (26.9318, -40.1354)
    point P1956 (26.9318, -40.1354)
    point P1957 (26.8609, -39.8756)
    point P1958 (26.8609, -39.8756)
    point P1959 (26.7895, -39.6305)
    point P1960 (26.7895, -39.6305)
    point P1961 (26.7179, -39.3999)
    point P1962 (26.7179, -39.3999)
    point P1963 (26.6466, -39.1838)
    point P1964 (26.6466, -39.1838)
    point P1969 (27.6227, -38.373)
    point P1970 (27.6227, -38.373)
    point P1971 (27.7947, -38.5111)
    point P1972 (27.7947, -38.5111)
    point P1973 (27.9801, -38.6546)
    point P1974 (27.9801, -38.6546)
    point P1975 (28.1791, -38.8032)
    point P1976 (28.1791, -38.8032)
    point P1977 (28.392, -38.9565)
    point P1978 (28.392, -38.9565)
    point P1979 (28.619, -39.1139)
    point P1980 (28.619, -39.1139)
    point P1981 (28.8602, -39.2751)
    point P1982 (28.8602, -39.2751)
    point P1983 (29.1159, -39.4396)
    point P1984 (29.1159, -39.4396)
    point P1985 (29.3863, -39.6069)
    point P1986 (29.3863, -39.6069)
    point P1987 (29.6715, -39.7765)
    point P1988 (29.6715, -39.7765)
    point P1989 (29.9716, -39.9481)
    point P1990 (29.9716, -39.9481)
    point P1991 (30.106, -40.0218)
    point P1992 (30.106, -40.0218)
    point P1993 (30.1217, -40.0285)
    point P1994 (30.1217, -40.0285)
    point P1995 (30.212, -40.0482)
    point P1996 (30.212, -40.0482)
    point P1997 (30.4419, -40.011)
    point P1998 (30.4419, -40.011)
    point P2003 (30.8384, -39.6401)
    point P2004 (30.8384, -39.6401)
    point P2005 (30.8696, -39.4886)
    point P2006 (30.8696, -39.4886)
    point P2007 (30.8666, -39.4408)
    point P2008 (30.8666, -39.4408)
    point P2009 (30.8611, -39.4164)
    point P2010 (30.8611, -39.4164)
    point P2011 (30.786, -39.1207)
    point P2012 (30.786, -39.1207)
    point P2013 (30.6968, -38.7938)
    point P2014 (30.6968, -38.7938)
    point P2015 (30.6059, -38.4819)
    point P2016 (30.6059, -38.4819)
    point P2017 (30.5137, -38.1849)
    point P2018 (30.5137, -38.1849)
    point P2019 (30.4207, -37.9027)
    point P2020 (30.4207, -37.9027)
    point P2021 (30.3273, -37.6354)
    point P2022 (30.3273, -37.6354)
    point P2023 (30.2341, -37.3828)
    point P2024 (30.2341, -37.3828)
    point P2025 (30.1416, -37.1448)
    point P2026 (30.1416, -37.1448)
    point P2027 (30.0502, -36.9214)
    point P2028 (30.0502, -36.9214)
    point P2029 (29.9603, -36.7123)
    point P2030 (29.9603, -36.7123)
    point P2031 (29.9026, -36.5841)
    point P2032 (29.9026, -36.5841)
    point P2035 (30.862, -35.8195)
    point P2036 (30.862, -35.8195)
    point P2037 (31.0454, -35.942)
    point P2038 (31.0454, -35.942)
    point P2039 (31.2426, -36.0689)
    point P2040 (31.2426, -36.0689)
    point P2041 (31.4538, -36.1996)
    point P2042 (31.4538, -36.1996)
    point P2043 (31.6793, -36.3337)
